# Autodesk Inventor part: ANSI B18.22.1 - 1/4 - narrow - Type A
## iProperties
Comments: To add or edit properties for Autodesk Inventor files, use iProperties.
Created: 2005-06
Part Number: ANSI B18.22.1 - 1/4 - narrow - Type A
Vendor: Autodesk Inc.
Document SubType Name: Modeling
Designer: John Blackburn
Material: Default
Description: Washer A
Standard: ANSI B18.22.1
Size Designation: 1/4 - narrow - Type A
Alert: To add or edit properties for Autodesk Inventor files, use iProperties.
Control State: 0
Master: False
Checked Out: False
Shininess: 64.0
Length Units: 11272
Angle Units: 11279
Time Units: 11290
Mass Units: 11286
Length Display Precision: 3
Angle Display Precision: 2
Compacted: True
Classification: un/spsc 31161807
Density: 0.0
Volumn: 0.0
Area: 0.0
PropertySet Name: Model Information
Author: John Blackburn
Revision Number: 8
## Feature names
1. Body [Extrusion]
